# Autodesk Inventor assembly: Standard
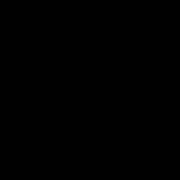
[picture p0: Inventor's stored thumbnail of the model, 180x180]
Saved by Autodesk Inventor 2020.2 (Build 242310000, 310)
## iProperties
Part Number: Standard
Document SubType Name: Assembly
Created: 2016-06
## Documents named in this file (1)
- C:\Users\Public\Documents\Autodesk\Inventor 2020\Templates\Standard.iam
